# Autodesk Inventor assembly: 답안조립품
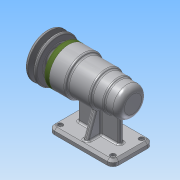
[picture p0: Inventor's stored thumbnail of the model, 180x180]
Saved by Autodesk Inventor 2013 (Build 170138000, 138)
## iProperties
Created: 2016-06
Part Number: 답안조립품
Document SubType Name: Assembly
Designer: Administrator
Author: Administrator
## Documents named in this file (10)
- C:\Users\Administrator\Desktop\460608V1017\답안조립품.iam
- C:\Users\Administrator\Desktop\460608V1017\본체.ipt
- C:\Users\Administrator\Desktop\460608V1017\베어링 51202.ipt
- C:\Users\Administrator\Desktop\460608V1017\어댑터슬리브.ipt
- C:\Users\Administrator\Desktop\460608V1017\축.ipt
- C:\Users\Administrator\Desktop\460608V1017\베어링 6004.ipt
- C:\Users\Administrator\Desktop\460608V1017\볼트 M4 x 12.ipt
- C:\Users\Administrator\Desktop\460608V1017\커버.ipt
- C:\Users\Administrator\Desktop\460608V1017\키 5 x 5 x 16.ipt
- C:\Users\Administrator\Desktop\460608V1017\V벨트풀리.ipt
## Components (6 placed, 2 different names)
1. ISO 4762 M4 x 12:1
2. V벨트풀리:1 — 각도:1
3. ISO 4762 M4 x 12:2
4. ISO 4762 M4 x 12:3
5. ISO 4762 M4 x 12:4
6. ISO 4762 M4 x 12:5
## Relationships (1: Angle 1)
- 각도:1 [Angle]: V벨트풀리:1
